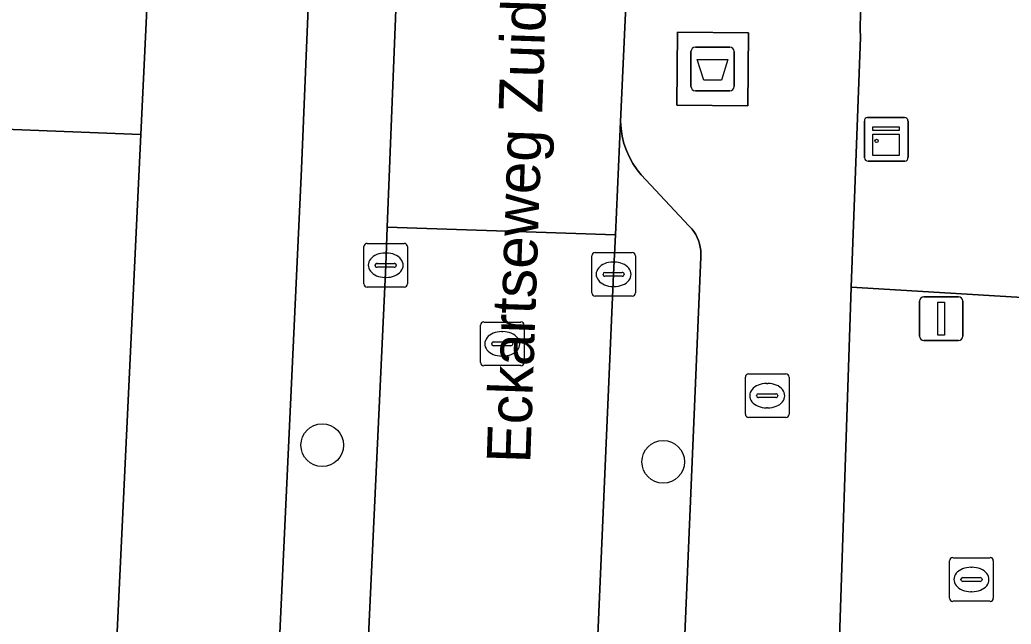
# Model space of a CAD drawing. Extents: x 161248 to 161848, y 384871 to 385383.
# Drawn here: x 161640.06 to 161662.78, y 384919.64 to 384933.48 of the extents above; entities that cross this region are included whole.
import ezdxf

# ---------------------------------------------------------------- set-up
doc = ezdxf.new("R2010")
doc.units = 0
for name, color, linetype in [('IMGEO_Afval_apart_plaats', 7, 'Continuous'), ('IMGEO_Boom', 7, 'Continuous'), ('IMGEO_Brandkraan', 7, 'Continuous'), ('IMGEO_Groenvoorziening', 7, 'Continuous'), ('IMGEO_Kast', 7, 'Continuous'), ('IMGEO_Kolk', 7, 'Continuous'), ('IMGEO_Lichtmast', 7, 'Continuous'), ('IMGEO_Openbare_ruimte_label', 7, 'Continuous'), ('IMGEO_Parkeervlak_open', 7, 'Continuous'), ('IMGEO_Rijbaan_lokaal_open', 7, 'Continuous'), ('IMGEO_Rioolput', 7, 'Continuous'), ('IMGEO_Voetpad_gesloten', 7, 'Continuous'), ('IMGEO_Voetpad_open', 7, 'Continuous')]:
    doc.layers.add(name, color=color, linetype=linetype)

msp = doc.modelspace()

# ---------------------------------------------------------------- linework, layer by layer
at = {"layer": 'IMGEO_Afval_apart_plaats'}
for p, q in [((161655.442, 384931.957), (161655.442, 384932.757)), ((161655.442, 384932.757), (161655.442, 384931.957)), ((161655.542, 384932.857), (161656.332, 384932.857)), ((161656.332, 384932.857), (161655.542, 384932.857)), ((161656.432, 384932.757), (161656.432, 384931.957)), ((161656.432, 384931.957), (161656.432, 384932.757)), ((161656.332, 384931.857), (161655.542, 384931.857)), ((161655.542, 384931.857), (161656.332, 384931.857))]:
    msp.add_line(p, q, dxfattribs=at)
msp.add_lwpolyline([(161655.585, 384932.571), (161656.289, 384932.571), (161656.14, 384932.101), (161655.734, 384932.101), (161655.585, 384932.571)], dxfattribs=at)
for centre, start, end in [((161655.542, 384932.757), 90, 180), ((161655.542, 384932.757), 90, 180), ((161656.332, 384932.757), 0, 90), ((161656.332, 384932.757), 360, 90), ((161655.542, 384931.957), 180, 270), ((161655.542, 384931.957), 180, 270), ((161656.332, 384931.957), 270, 0), ((161656.332, 384931.957), 270, 0)]:
    msp.add_arc(centre, 0.1, start, end, dxfattribs=at)
at = {"layer": 'IMGEO_Boom'}
for centre in [(161646.992, 384923.739), (161654.806, 384923.355)]:
    msp.add_circle(centre, 0.489, dxfattribs=at)
at = {"layer": 'IMGEO_Brandkraan'}
for p, q in [((161656.688, 384924.447), (161656.688, 384925.299)), ((161656.763, 384925.373), (161657.615, 384925.373)), ((161657.689, 384925.299), (161657.689, 384924.447)), ((161657.176, 384925.153), (161657.201, 384925.153)), ((161656.947, 384924.867), (161656.947, 384924.879)), ((161657.385, 384924.83), (161656.987, 384924.83)), ((161656.99, 384924.916), (161657.388, 384924.916)), ((161657.431, 384924.879), (161657.431, 384924.867)), ((161657.199, 384924.593), (161657.174, 384924.593)), ((161657.615, 384924.373), (161656.763, 384924.373))]:
    msp.add_line(p, q, dxfattribs=at)
for points in [[(161656.688, 384924.447), (161656.688, 384925.299)], [(161656.763, 384925.373), (161657.615, 384925.373)], [(161657.689, 384925.299), (161657.689, 384924.447)], [(161657.615, 384924.373), (161656.763, 384924.373)]]:
    msp.add_lwpolyline(points, dxfattribs=at)
for centre, radius, start, end in [((161656.765, 384925.297), 0.0765, 91.552, 178.448), ((161656.765, 384925.297), 0.0765, 91.552, 178.448), ((161657.613, 384925.297), 0.0765, 1.552, 88.448), ((161657.613, 384925.297), 0.0765, 1.552, 88.448), ((161656.987, 384924.876), 0.0403, 85.8775, 175.7526), ((161656.984, 384924.866), 0.0366, 178.938, 274.7102), ((161657.388, 384924.873), 0.043, 264.8664, 352.4533), ((161657.392, 384924.878), 0.0386, 1.7309, 96.639), ((161656.765, 384924.449), 0.0765, 181.552, 268.448), ((161656.765, 384924.449), 0.0765, 181.552, 268.448), ((161657.613, 384924.449), 0.0765, 271.552, 358.448), ((161657.613, 384924.449), 0.0765, 271.552, 358.448)]:
    msp.add_arc(centre, radius, start, end, dxfattribs=at)
for centre, major_axis, ratio, start_param, end_param in [((161657.175, 384924.873), (-0.387, 0.002), 0.722429, 4.712389, 7.853982), ((161657.2, 384924.873), (-0.39, 0.002), 0.717154, 1.570796, 4.712389)]:
    msp.add_ellipse(centre, major_axis=major_axis, ratio=ratio, start_param=start_param, end_param=end_param, dxfattribs=at)
at = {"layer": 'IMGEO_Groenvoorziening'}
msp.add_lwpolyline([(161662.878, 384937.474), (161662.51, 384937.401), (161662.15, 384937.295), (161661.801, 384937.157), (161661.465, 384936.988), (161661.146, 384936.791), (161660.846, 384936.565), (161660.567, 384936.314), (161660.312, 384936.039), (161660.082, 384935.742), (161659.88, 384935.426), (161659.707, 384935.093), (161659.564, 384934.745), (161659.453, 384934.387), (161659.374, 384934.02), (161659.329, 384933.647), (161659.316, 384933.272), (161659.323, 384933.077), (161659.115, 384927.361), (161663.663, 384927.082)], dxfattribs=at)
at = {"layer": 'IMGEO_Kast'}
for p, q in [((161659.415, 384930.32), (161659.415, 384931.161)), ((161659.415, 384931.161), (161659.415, 384930.32)), ((161659.49, 384931.245), (161660.331, 384931.245)), ((161660.331, 384931.245), (161659.49, 384931.245)), ((161660.415, 384931.17), (161660.415, 384930.329)), ((161660.415, 384930.329), (161660.415, 384931.17)), ((161660.34, 384930.245), (161659.499, 384930.245)), ((161659.499, 384930.245), (161660.34, 384930.245))]:
    msp.add_line(p, q, dxfattribs=at)
for points in [[(161659.61, 384931.035), (161660.21, 384931.035), (161660.21, 384930.95), (161659.61, 384930.95), (161659.61, 384931.035)], [(161659.61, 384930.86), (161660.21, 384930.86), (161660.21, 384930.371), (161659.61, 384930.371), (161659.61, 384930.86)]]:
    msp.add_lwpolyline(points, dxfattribs=at)
msp.add_circle((161659.694, 384930.709), 0.0377, dxfattribs=at)
for centre, start, end in [((161659.493, 384931.167), 92.4484, 184.2845), ((161659.493, 384931.167), 92.4484, 184.2845), ((161660.337, 384931.167), 2.4484, 94.2845), ((161660.337, 384931.167), 2.4484, 94.2845), ((161659.493, 384930.323), 182.4484, 274.2845), ((161659.493, 384930.323), 182.4484, 274.2845), ((161660.337, 384930.323), 272.4484, 4.2845), ((161660.337, 384930.323), 272.4484, 4.2845)]:
    msp.add_arc(centre, 0.0779, start, end, dxfattribs=at)
at = {"layer": 'IMGEO_Kolk'}
for p, q in [((161648.02, 384928.361), (161648.872, 384928.361)), ((161647.945, 384927.435), (161647.945, 384928.287)), ((161648.433, 384928.141), (161648.458, 384928.141)), ((161648.946, 384928.287), (161648.946, 384927.435)), ((161653.243, 384928.153), (161654.095, 384928.153)), ((161648.247, 384927.904), (161648.645, 384927.904)), ((161653.168, 384927.227), (161653.168, 384928.079)), ((161653.656, 384927.933), (161653.681, 384927.933)), ((161654.169, 384928.079), (161654.169, 384927.227)), ((161648.204, 384927.855), (161648.204, 384927.867)), ((161648.642, 384927.818), (161648.244, 384927.818)), ((161648.688, 384927.867), (161648.688, 384927.855)), ((161653.47, 384927.696), (161653.868, 384927.696)), ((161648.456, 384927.581), (161648.431, 384927.581)), ((161653.427, 384927.647), (161653.427, 384927.659)), ((161653.865, 384927.61), (161653.467, 384927.61)), ((161653.911, 384927.659), (161653.911, 384927.647)), ((161648.872, 384927.361), (161648.02, 384927.361)), ((161653.679, 384927.373), (161653.654, 384927.373)), ((161654.095, 384927.153), (161653.243, 384927.153)), ((161661.369, 384920.235), (161661.369, 384921.087)), ((161661.444, 384921.161), (161662.296, 384921.161)), ((161662.37, 384921.087), (161662.37, 384920.235)), ((161661.857, 384920.941), (161661.882, 384920.941)), ((161661.628, 384920.655), (161661.628, 384920.667)), ((161661.671, 384920.704), (161662.069, 384920.704)), ((161662.112, 384920.667), (161662.112, 384920.655)), ((161662.066, 384920.618), (161661.668, 384920.618)), ((161661.88, 384920.381), (161661.855, 384920.381)), ((161662.296, 384920.161), (161661.444, 384920.161))]:
    msp.add_line(p, q, dxfattribs=at)
for points in [[(161648.02, 384928.361), (161648.872, 384928.361)], [(161647.945, 384927.435), (161647.945, 384928.287)], [(161648.946, 384928.287), (161648.946, 384927.435)], [(161653.243, 384928.153), (161654.095, 384928.153)], [(161653.168, 384927.227), (161653.168, 384928.079)], [(161654.169, 384928.079), (161654.169, 384927.227)], [(161648.872, 384927.361), (161648.02, 384927.361)], [(161654.095, 384927.153), (161653.243, 384927.153)], [(161661.369, 384920.235), (161661.369, 384921.087)], [(161661.444, 384921.161), (161662.296, 384921.161)], [(161662.37, 384921.087), (161662.37, 384920.235)], [(161662.296, 384920.161), (161661.444, 384920.161)]]:
    msp.add_lwpolyline(points, dxfattribs=at)
for centre, radius, start, end in [((161648.022, 384928.285), 0.0765, 91.552, 178.448), ((161648.022, 384928.285), 0.0765, 91.552, 178.448), ((161648.87, 384928.285), 0.0765, 1.552, 88.448), ((161648.87, 384928.285), 0.0765, 1.552, 88.448), ((161653.245, 384928.077), 0.0765, 91.552, 178.448), ((161653.245, 384928.077), 0.0765, 91.552, 178.448), ((161654.093, 384928.077), 0.0765, 1.552, 88.448), ((161654.093, 384928.077), 0.0765, 1.552, 88.448), ((161648.244, 384927.864), 0.0403, 85.8775, 175.7526), ((161648.649, 384927.866), 0.0386, 1.7309, 96.639), ((161648.241, 384927.854), 0.0366, 178.938, 274.7102), ((161648.645, 384927.861), 0.043, 264.8664, 352.4533), ((161653.467, 384927.656), 0.0403, 85.8775, 175.7526), ((161653.872, 384927.658), 0.0386, 1.7309, 96.639), ((161653.464, 384927.646), 0.0366, 178.938, 274.7102), ((161653.868, 384927.653), 0.043, 264.8664, 352.4533), ((161648.022, 384927.437), 0.0765, 181.552, 268.448), ((161648.022, 384927.437), 0.0765, 181.552, 268.448), ((161648.87, 384927.437), 0.0765, 271.552, 358.448), ((161648.87, 384927.437), 0.0765, 271.552, 358.448), ((161653.245, 384927.229), 0.0765, 181.552, 268.448), ((161653.245, 384927.229), 0.0765, 181.552, 268.448), ((161654.093, 384927.229), 0.0765, 271.552, 358.448), ((161654.093, 384927.229), 0.0765, 271.552, 358.448), ((161661.446, 384921.085), 0.0765, 91.552, 178.448), ((161661.446, 384921.085), 0.0765, 91.552, 178.448), ((161662.294, 384921.085), 0.0765, 1.552, 88.448), ((161662.294, 384921.085), 0.0765, 1.552, 88.448), ((161661.668, 384920.664), 0.0403, 85.8775, 175.7526), ((161661.665, 384920.654), 0.0366, 178.938, 274.7102), ((161662.069, 384920.661), 0.043, 264.8664, 352.4533), ((161662.073, 384920.666), 0.0386, 1.7309, 96.639), ((161661.446, 384920.237), 0.0765, 181.552, 268.448), ((161661.446, 384920.237), 0.0765, 181.552, 268.448), ((161662.294, 384920.237), 0.0765, 271.552, 358.448), ((161662.294, 384920.237), 0.0765, 271.552, 358.448)]:
    msp.add_arc(centre, radius, start, end, dxfattribs=at)
for centre, major_axis, ratio, start_param, end_param in [((161648.432, 384927.861), (-0.387, 0.002), 0.722429, 4.712389, 7.853982), ((161648.457, 384927.861), (-0.39, 0.002), 0.717154, 1.570796, 4.712389), ((161653.655, 384927.653), (-0.387, 0.002), 0.722429, 4.712389, 7.853982), ((161653.68, 384927.653), (-0.39, 0.002), 0.717154, 1.570796, 4.712389), ((161661.856, 384920.661), (-0.387, 0.002), 0.722429, 4.712389, 7.853982), ((161661.881, 384920.661), (-0.39, 0.002), 0.717154, 1.570796, 4.712389)]:
    msp.add_ellipse(centre, major_axis=major_axis, ratio=ratio, start_param=start_param, end_param=end_param, dxfattribs=at)
at = {"layer": 'IMGEO_Lichtmast'}
for p, q in [((161660.679, 384926.237), (161660.679, 384927.037)), ((161660.679, 384927.037), (161660.679, 384926.237)), ((161660.779, 384927.137), (161661.569, 384927.137)), ((161661.569, 384927.137), (161660.779, 384927.137)), ((161661.669, 384927.037), (161661.669, 384926.237)), ((161661.669, 384926.237), (161661.669, 384927.037)), ((161661.569, 384926.137), (161660.779, 384926.137)), ((161660.779, 384926.137), (161661.569, 384926.137))]:
    msp.add_line(p, q, dxfattribs=at)
msp.add_lwpolyline([(161661.099, 384927.012), (161661.249, 384927.012), (161661.249, 384926.262), (161661.099, 384926.262), (161661.099, 384927.012)], dxfattribs=at)
for centre, start, end in [((161660.779, 384927.037), 90, 180), ((161660.779, 384927.037), 90, 180), ((161661.569, 384927.037), 0, 90), ((161661.569, 384927.037), 360, 90), ((161660.779, 384926.237), 180, 270), ((161660.779, 384926.237), 180, 270), ((161661.569, 384926.237), 270, 0), ((161661.569, 384926.237), 270, 0)]:
    msp.add_arc(centre, 0.1, start, end, dxfattribs=at)
at = {"layer": 'IMGEO_Parkeervlak_open'}
for points in [[(161648.481, 384928.734), (161648.985, 384941.37), (161649.637, 384956.361), (161647.607, 384956.463), (161646.514, 384930.067), (161645.098, 384899.633), (161645.098, 384899.539), (161645.105, 384899.445), (161645.121, 384899.352), (161645.145, 384899.261), (161645.177, 384899.172), (161645.217, 384899.087), (161645.265, 384899.005), (161645.319, 384898.928), (161645.34, 384898.902), (161646.493, 384897.433)], [(161654.441, 384899.044), (161655.664, 384928.043), (161655.668, 384928.12), (161655.665, 384928.198), (161655.656, 384928.275), (161655.64, 384928.351), (161655.616, 384928.425), (161655.587, 384928.496), (161655.551, 384928.565), (161655.509, 384928.63), (161655.462, 384928.691), (161655.409, 384928.748), (161655.392, 384928.764), (161654.304, 384929.932), (161654.209, 384930.048), (161654.113, 384930.189), (161654.03, 384930.337), (161653.961, 384930.492), (161653.906, 384930.653), (161653.866, 384930.818), (161653.84, 384930.986), (161653.829, 384931.155), (161653.71, 384928.556), (161653.669, 384927.653), (161653.069, 384913.925)], [(161646.925, 384896.2), (161646.952, 384896.731), (161647.114, 384899.951), (161647.804, 384914.139), (161648.446, 384927.861), (161648.481, 384928.734)]]:
    msp.add_lwpolyline(points, dxfattribs=at)
msp.add_lwpolyline([(161642.834, 384930.859), (161637.178, 384931.075), (161635.564, 384892.394), (161638.835, 384892.252), (161639.071, 384892.296), (161639.303, 384892.361), (161639.528, 384892.447), (161639.744, 384892.552), (161639.95, 384892.677), (161640.144, 384892.819), (161640.324, 384892.978), (161640.49, 384893.152), (161640.639, 384893.341), (161640.771, 384893.542), (161640.885, 384893.754), (161640.979, 384893.975), (161641.053, 384894.204), (161641.1, 384894.408), (161641.274, 384898.125)], close=True, dxfattribs=at)
at = {"layer": 'IMGEO_Rijbaan_lokaal_open'}
msp.add_lwpolyline([(161648.985, 384941.37), (161648.481, 384928.734), (161653.71, 384928.556), (161653.829, 384931.155), (161654.012, 384935.141)], dxfattribs=at)
for points in [[(161631.414, 384936.475), (161629.419, 384892.66), (161635.564, 384892.394), (161637.178, 384931.075), (161642.834, 384930.859), (161643.076, 384935.977)], [(161653.71, 384928.556), (161648.481, 384928.734), (161648.446, 384927.861), (161647.804, 384914.139), (161647.114, 384899.951), (161646.952, 384896.731), (161652.306, 384896.47), (161653.069, 384913.925), (161653.669, 384927.653)]]:
    msp.add_lwpolyline(points, close=True, dxfattribs=at)
at = {"layer": 'IMGEO_Rioolput'}
for p, q in [((161650.691, 384926.56), (161651.543, 384926.56)), ((161650.616, 384925.634), (161650.616, 384926.486)), ((161651.104, 384926.34), (161651.129, 384926.34)), ((161651.617, 384926.486), (161651.617, 384925.634)), ((161650.918, 384926.103), (161651.316, 384926.103)), ((161650.875, 384926.054), (161650.875, 384926.066)), ((161651.313, 384926.017), (161650.915, 384926.017)), ((161651.359, 384926.066), (161651.359, 384926.054)), ((161651.127, 384925.78), (161651.102, 384925.78)), ((161651.543, 384925.56), (161650.691, 384925.56))]:
    msp.add_line(p, q, dxfattribs=at)
for points in [[(161650.691, 384926.56), (161651.543, 384926.56)], [(161650.616, 384925.634), (161650.616, 384926.486)], [(161651.617, 384926.486), (161651.617, 384925.634)], [(161651.543, 384925.56), (161650.691, 384925.56)]]:
    msp.add_lwpolyline(points, dxfattribs=at)
for centre, radius, start, end in [((161650.693, 384926.484), 0.0765, 91.552, 178.448), ((161650.693, 384926.484), 0.0765, 91.552, 178.448), ((161651.541, 384926.484), 0.0765, 1.552, 88.448), ((161651.541, 384926.484), 0.0765, 1.552, 88.448), ((161650.915, 384926.063), 0.0403, 85.8775, 175.7526), ((161651.32, 384926.065), 0.0386, 1.7309, 96.639), ((161650.912, 384926.053), 0.0366, 178.938, 274.7102), ((161651.316, 384926.06), 0.043, 264.8664, 352.4533), ((161650.693, 384925.636), 0.0765, 181.552, 268.448), ((161650.693, 384925.636), 0.0765, 181.552, 268.448), ((161651.541, 384925.636), 0.0765, 271.552, 358.448), ((161651.541, 384925.636), 0.0765, 271.552, 358.448)]:
    msp.add_arc(centre, radius, start, end, dxfattribs=at)
for centre, major_axis, ratio, start_param, end_param in [((161651.103, 384926.06), (-0.387, 0.002), 0.722429, 4.712389, 7.853982), ((161651.128, 384926.06), (-0.39, 0.002), 0.717154, 1.570796, 4.712389)]:
    msp.add_ellipse(centre, major_axis=major_axis, ratio=ratio, start_param=start_param, end_param=end_param, dxfattribs=at)
at = {"layer": 'IMGEO_Voetpad_gesloten'}
msp.add_lwpolyline([(161656.76, 384933.186), (161655.131, 384933.203), (161655.114, 384931.528), (161656.743, 384931.511)], close=True, dxfattribs=at)
at = {"layer": 'IMGEO_Voetpad_open'}
for points in [[(161645.098, 384899.633), (161646.514, 384930.067), (161647.607, 384956.463)], [(161643.704, 384949.599), (161643.39, 384942.788), (161643.076, 384935.977), (161642.834, 384930.859), (161641.274, 384898.125)], [(161654.012, 384935.141), (161653.829, 384931.155), (161653.84, 384930.986), (161653.866, 384930.818), (161653.906, 384930.653), (161653.961, 384930.492), (161654.03, 384930.337), (161654.113, 384930.189), (161654.209, 384930.048), (161654.304, 384929.932), (161655.392, 384928.764), (161655.409, 384928.748), (161655.462, 384928.691), (161655.509, 384928.63), (161655.551, 384928.565), (161655.587, 384928.496), (161655.616, 384928.425), (161655.64, 384928.351), (161655.656, 384928.275), (161655.665, 384928.198), (161655.668, 384928.12), (161655.664, 384928.043), (161654.441, 384899.044)], [(161658.454, 384907.625), (161659.115, 384927.361), (161659.323, 384933.077), (161659.316, 384933.272), (161659.329, 384933.647)], [(161704.973, 384925.573), (161667.878, 384926.869), (161663.663, 384927.082), (161659.115, 384927.361), (161658.454, 384907.625)]]:
    msp.add_lwpolyline(points, dxfattribs=at)
msp.add_lwpolyline([(161655.114, 384931.528), (161655.131, 384933.203), (161656.76, 384933.186), (161656.743, 384931.511)], close=True, dxfattribs=at)

# ---------------------------------------------------------------- texts
at = {"layer": 'IMGEO_Openbare_ruimte_label'}
msp.add_text('Eckartseweg Zuid', height=1, rotation=88.0507, dxfattribs=at).set_placement((161651.758, 384923.312))

doc.saveas('drawing.dxf')
